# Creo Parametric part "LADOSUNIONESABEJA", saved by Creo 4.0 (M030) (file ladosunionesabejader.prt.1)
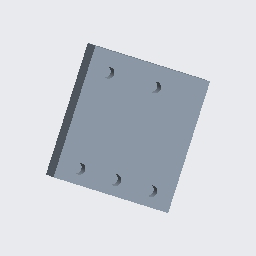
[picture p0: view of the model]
Units: millimeter Newton Second (mmNs); MM, TONNE, SECS

Created from: MMNS_PART_SOLID.PRT

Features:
  1. datum plane "RIGHT"
  2. datum plane "TOP"
  3. datum plane "FRONT"
  4. coordinate system
  5. sketch "Sketch 1"
  6. extrusion "Extrude 1"
  7. pattern "Pattern 1"
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
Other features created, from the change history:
  hole "Hole 1"
  hole "Hole 1 [2]"
  hole "Hole 1 [3]"
  hole "Hole 2"
  pattern "Patrón 2"
  hole "Taladro 2 [2]"
  hole "Hole 3"
  pattern "Pattern 3"
  hole "Hole 3 [2]"

Surfaces: 13 plane, 7 cylinder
